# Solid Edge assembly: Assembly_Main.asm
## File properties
Author: hhakima
Template: Normal.asm
Last saved by: Houman
Revision: 38
Application: Solid Edge
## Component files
Part - Lower Plate.par
Part - Stand Off.par
PCB.par
Screw_M1.6_6MM.par
Part - Top Plate.par
DM_LD_Prism.asm
Part - Rear Cap.par
Part - Front Cap.par
Screw_M2_6MM_mir.par
Ray - Green.par
Ray - Blue.par
Ray - Yellow.par
Ray - Red.par
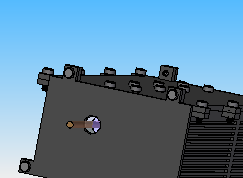
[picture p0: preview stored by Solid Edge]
